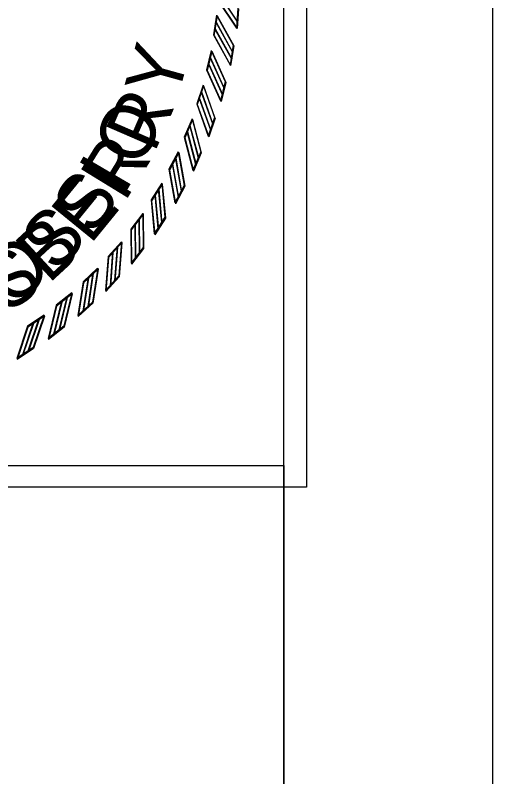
# Model space of a CAD drawing. Extents: x 0 to 1228740, y 0 to 152440.
# Drawn here: x 32.682 to 34, y 16.545 to 18.648 of the extents above; entities that cross this region are included whole.
import ezdxf

# ---------------------------------------------------------------- set-up
doc = ezdxf.new("R2010")
doc.units = 0
for name, color, linetype in [('R_Border', 7, 'Continuous'), ('R_No Plot', 7, 'Continuous'), ('STAMP', 7, 'Continuous'), ('STAMP_SWB', 7, 'Continuous')]:
    doc.layers.add(name, color=color, linetype=linetype)

msp = doc.modelspace()

# ---------------------------------------------------------------- linework, layer by layer
at = {"layer": 'R_Border'}
msp.add_line((33.4231, 0.5768), (33.4231, 21.4232), dxfattribs=at)
msp.add_lwpolyline([(34, 22), (0, 22), (0, 0), (34, 0)], close=True, dxfattribs=at)
at = {"layer": 'R_No Plot'}
for points in [[(33.4231, 17.4052), (33.4231, 10.8708), (1.516, 10.8708), (1.516, 21.4232), (25.1971, 21.4232), (25.1971, 20.4352), (28.7491, 20.4352), (28.7491, 20.0782), (29.1131, 20.0782), (29.1131, 20.1432), (30.6665, 20.1432)], [(33.4231, 17.4052), (33.4231, 0.6568), (1.516, 0.6568), (1.516, 21.4232), (25.1971, 21.4232), (25.1971, 20.4352), (28.7491, 20.4352), (28.7491, 20.0782), (29.1131, 20.0782), (29.1131, 20.1432), (30.6665, 20.1432)], [(30.6665, 20.1432), (30.6665, 17.4052), (33.4231, 17.4052)], [(30.6665, 20.1432), (30.6665, 17.4052), (33.4231, 17.4052)]]:
    msp.add_lwpolyline(points, dxfattribs=at)
msp.add_lwpolyline([(30.6265, 20.205), (33.4865, 20.205), (33.4865, 17.3449), (30.6265, 17.3449)], close=True, dxfattribs=at)
msp.add_lwpolyline([(30.6265, 20.205), (33.4865, 20.205), (33.4865, 17.3449), (30.6265, 17.3449)], close=True, dxfattribs=at)
at = {"layer": 'STAMP'}
for p, q in [((33.297, 18.6673), (33.293, 18.6128)), ((33.2379, 18.6478), (33.2294, 18.5938)), ((33.2233, 18.5507), (33.2103, 18.4975)), ((33.2837, 18.5652), (33.2753, 18.5113)), ((33.2621, 18.4646), (33.2492, 18.4115)), ((33.2007, 18.4551), (33.1834, 18.4032)), ((33.1702, 18.3617), (33.1487, 18.3114)), ((33.2322, 18.3661), (33.215, 18.3143)), ((33.1322, 18.2712), (33.1066, 18.2228)), ((33.1943, 18.2704), (33.1729, 18.2202)), ((33.0868, 18.1841), (33.0573, 18.138)), ((33.1487, 18.1782), (33.1231, 18.1299)), ((33.0343, 18.101), (33.0011, 18.0575)), ((33.0955, 18.09), (33.0661, 18.044)), ((32.9752, 18.0226), (32.9385, 17.982)), ((33.0353, 18.0066), (33.0022, 17.9632)), ((32.9098, 17.9493), (32.8699, 17.9119)), ((32.9684, 17.9284), (32.9318, 17.8878)), ((32.8386, 17.8817), (32.7958, 17.8477)), ((32.8952, 17.856), (32.8554, 17.8186)), ((32.7621, 17.8201), (32.7165, 17.7898)), ((32.8164, 17.7898), (32.7736, 17.7559)), ((32.7323, 17.7305), (32.6869, 17.7002))]:
    msp.add_line(p, q, dxfattribs=at)
for points in [[(33.2421, 18.7094), (33.2945, 18.6309)], [(33.2405, 18.6913), (33.293, 18.6127)], [(33.235, 18.6306), (33.2808, 18.5479)], [(33.2379, 18.6479), (33.2837, 18.5653)], [(33.2325, 18.6118), (33.2783, 18.5291)], [(33.2295, 18.5938), (33.2753, 18.5112)], [(33.2232, 18.5508), (33.2621, 18.4647)], [(33.2189, 18.5337), (33.2578, 18.4476)], [(33.2149, 18.5152), (33.2537, 18.4291)], [(33.2104, 18.4976), (33.2492, 18.4115)], [(33.2006, 18.4552), (33.2322, 18.3662)], [(33.1893, 18.4205), (33.2209, 18.3314)], [(33.1949, 18.4386), (33.2265, 18.3495)], [(33.1834, 18.4033), (33.215, 18.3142)], [(33.1702, 18.3618), (33.1943, 18.2705)], [(33.1631, 18.3457), (33.1873, 18.2544)], [(33.1561, 18.3281), (33.1802, 18.2368)], [(33.1488, 18.3115), (33.1729, 18.2201)], [(33.1238, 18.2558), (33.1403, 18.1628)], [(33.1322, 18.2713), (33.1487, 18.1782)], [(33.1153, 18.2389), (33.1318, 18.1458)], [(33.1066, 18.2229), (33.1231, 18.1298)], [(33.0772, 18.1695), (33.0859, 18.0754)], [(33.0868, 18.1842), (33.0955, 18.0901)], [(33.0673, 18.1533), (33.076, 18.0592)], [(33.0573, 18.138), (33.0661, 18.044)], [(33.0235, 18.0872), (33.0245, 17.9928)], [(33.0343, 18.1011), (33.0353, 18.0066)], [(33.0124, 18.0719), (33.0133, 17.9775)], [(33.0012, 18.0576), (33.0022, 17.9631)], [(32.9752, 18.0227), (32.9684, 17.9285)], [(32.9633, 18.0097), (32.9565, 17.9155)], [(32.9386, 17.982), (32.9318, 17.8878)], [(32.9509, 17.9954), (32.9441, 17.9012)], [(32.8969, 17.9375), (32.8823, 17.8441)], [(32.9099, 17.9494), (32.8953, 17.856)], [(32.8834, 17.9242), (32.8688, 17.8309)], [(32.87, 17.9119), (32.8554, 17.8185)], [(32.8386, 17.8817), (32.8164, 17.7899)], [(32.8102, 17.8588), (32.7879, 17.767)], [(32.8248, 17.8709), (32.8025, 17.7791)], [(32.7958, 17.8477), (32.7736, 17.7558)], [(32.7474, 17.8106), (32.7176, 17.7209)], [(32.7621, 17.8202), (32.7323, 17.7305)], [(32.7166, 17.7898), (32.6868, 17.7001)], [(32.7318, 17.7997), (32.7021, 17.7101)]]:
    msp.add_lwpolyline(points, dxfattribs=at)
at = {"layer": 'STAMP_SWB'}
for p, q in [((33.2985, 18.6656), (33.2945, 18.6111)), ((33.2394, 18.6461), (33.2308, 18.592)), ((33.2247, 18.5489), (33.2117, 18.4956)), ((33.2852, 18.5634), (33.2767, 18.5094)), ((33.2636, 18.4626), (33.2506, 18.4095)), ((33.202, 18.4532), (33.1847, 18.4012)), ((33.1716, 18.3597), (33.15, 18.3093)), ((33.2337, 18.364), (33.2164, 18.3121)), ((33.1335, 18.269), (33.1078, 18.2206)), ((33.1957, 18.2682), (33.1742, 18.2179)), ((33.088, 18.1818), (33.0585, 18.1356)), ((33.15, 18.1759), (33.1244, 18.1275)), ((33.0355, 18.0986), (33.0023, 18.0551)), ((33.0968, 18.0876), (33.0673, 18.0416)), ((32.9763, 18.0201), (32.9396, 17.9794)), ((33.0365, 18.004), (33.0033, 17.9606)), ((32.9108, 17.9467), (32.8709, 17.9092)), ((32.9695, 17.9257), (32.9328, 17.8852)), ((32.8395, 17.879), (32.7966, 17.8449)), ((32.8962, 17.8532), (32.8563, 17.8158)), ((32.7629, 17.8174), (32.7173, 17.787)), ((32.8172, 17.787), (32.7744, 17.7531)), ((32.7331, 17.7276), (32.6876, 17.6973))]:
    msp.add_line(p, q, dxfattribs=at)
for points in [[(33.2435, 18.7078), (33.296, 18.6292)], [(33.242, 18.6897), (33.2945, 18.611)], [(33.2393, 18.6462), (33.2852, 18.5635)], [(33.2339, 18.61), (33.2798, 18.5273)], [(33.2364, 18.6288), (33.2823, 18.5461)], [(33.2309, 18.5921), (33.2768, 18.5093)], [(33.2247, 18.549), (33.2635, 18.4627)], [(33.2203, 18.5319), (33.2592, 18.4457)], [(33.2163, 18.5133), (33.2551, 18.4271)], [(33.2118, 18.4957), (33.2507, 18.4095)], [(33.202, 18.4533), (33.2336, 18.3641)], [(33.1963, 18.4366), (33.2279, 18.3475)], [(33.1848, 18.4012), (33.2164, 18.3121)], [(33.1907, 18.4185), (33.2223, 18.3293)], [(33.1715, 18.3598), (33.1957, 18.2683)], [(33.1645, 18.3436), (33.1886, 18.2522)], [(33.1574, 18.326), (33.1815, 18.2346)], [(33.1501, 18.3093), (33.1742, 18.2179)], [(33.1251, 18.2536), (33.1416, 18.1605)], [(33.1334, 18.2691), (33.15, 18.1759)], [(33.1166, 18.2366), (33.1331, 18.1435)], [(33.1079, 18.2206), (33.1244, 18.1275)], [(33.0784, 18.1671), (33.0871, 18.073)], [(33.088, 18.1819), (33.0968, 18.0877)], [(33.0685, 18.1509), (33.0773, 18.0567)], [(33.0585, 18.1357), (33.0673, 18.0415)], [(33.0247, 18.0848), (33.0257, 17.9902)], [(33.0355, 18.0987), (33.0365, 18.0041)], [(33.0135, 18.0695), (33.0145, 17.9749)], [(33.0023, 18.0551), (33.0033, 17.9605)], [(32.9763, 18.0202), (32.9695, 17.9258)], [(32.9644, 18.0072), (32.9576, 17.9129)], [(32.9397, 17.9795), (32.9328, 17.8851)], [(32.952, 17.9929), (32.9451, 17.8985)], [(32.9109, 17.9468), (32.8962, 17.8533)], [(32.8843, 17.9216), (32.8697, 17.8281)], [(32.8979, 17.9349), (32.8833, 17.8414)], [(32.8709, 17.9092), (32.8563, 17.8158)], [(32.8396, 17.8791), (32.8173, 17.7871)], [(32.8111, 17.8561), (32.7888, 17.7642)], [(32.8257, 17.8683), (32.8034, 17.7763)], [(32.7967, 17.8449), (32.7744, 17.753)], [(32.7629, 17.8175), (32.7331, 17.7277)], [(32.7326, 17.7969), (32.7028, 17.7072)], [(32.7482, 17.8078), (32.7184, 17.7181)], [(32.7174, 17.787), (32.6876, 17.6972)]]:
    msp.add_lwpolyline(points, dxfattribs=at)

# ---------------------------------------------------------------- texts
at = {"layer": 'STAMP'}
for s, rotation, p in [('Y', 74.5264, (33.1283, 18.4107)), ('R', 66.5008, (33.0661, 18.2652)), ('R', 58.4752, (32.9843, 18.1298)), ('E', 50.8144, (32.8892, 18.0124)), ('B', 42.7888, (32.7738, 17.9042)), ('S', 35.4928, (32.6567, 17.8206))]:
    msp.add_text(s, height=0.1509, rotation=rotation, dxfattribs=at).set_placement(p)
at = {"layer": 'STAMP_SWB'}
for s, rotation, p in [('O', 64.0805, (33.0274, 18.2228)), ('I', 59.6477, (32.9819, 18.1494)), ('S', 52.2599, (32.8939, 18.0357)), ('S', 44.872, (32.792, 17.9342)), ('O', 36.7453, (32.6658, 17.8388))]:
    msp.add_text(s, height=0.1508, rotation=rotation, dxfattribs=at).set_placement(p)

doc.saveas('drawing.dxf')
